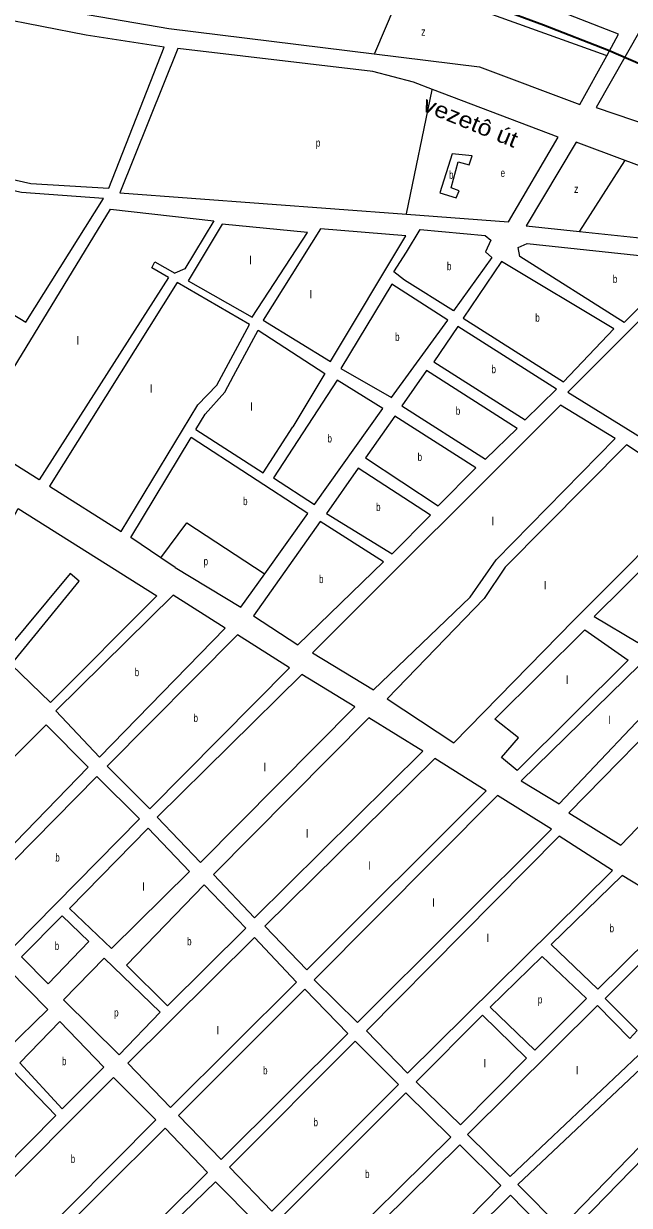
# Model space of a CAD drawing. Extents: x 639657 to 671642, y 222838 to 252123.
# Drawn here: x 657088 to 657845, y 234105 to 235581 of the extents above; entities that cross this region are included whole.
import ezdxf
from ezdxf.enums import TextEntityAlignment as Align

# ---------------------------------------------------------------- set-up
doc = ezdxf.new("R2010")
doc.units = 0
doc.header["$LTSCALE"] = 4
for name, color, linetype, lineweight in [('1', 7, 'Continuous', 13), ('21', 7, 'Continuous', 13), ('57', 7, 'Continuous', 35)]:
    doc.layers.add(name, color=color, linetype=linetype, lineweight=lineweight)
doc.layers.add('22', color=7, linetype='Continuous')
doc.layers.add('7', color=7, linetype='Continuous')

msp = doc.modelspace()

# ---------------------------------------------------------------- linework, layer by layer
at = {"layer": '1'}
for p, q in [((657269.75, 235574.98), (657526.201, 235543.425)), ((657859.39, 235575.31), (657803.218, 235476.576)), ((657944.6, 235370.82), (657839.364, 235410.339)), ((657269.084, 235264.14), (657248.416, 235276.078)), ((657277.55, 234901.85), (657259.832, 234913.783))]:
    msp.add_line(p, q, dxfattribs=at)
for points in [[(656309.705, 235813.299), (656445.06, 235807.97), (657053.16, 235612.8), (657269.75, 235574.98)], [(657194.55, 235375.68), (657263.9, 235551.99), (657166.35, 235566.78), (657055.12, 235588.31), (657016.883, 235600.33), (656903.413, 235635.999)], [(657816.457, 235541.231), (657831.17, 235567.96), (657721.89, 235611.16)], [(657524.2, 235521.65), (657281.04, 235550.05), (657208.54, 235369.83), (657566.169, 235343.122)], [(657526.201, 235543.425), (657657.619, 235527.255), (657782.961, 235480.377), (657816.457, 235541.231)], [(657598.63, 235499.04), (657574.98, 235508.03), (657524.2, 235521.65)], [(656958.68, 235507.97), (656957.78, 235467.15), (656935.92, 235426.78), (657028.98, 235397.06), (657097.28, 235381.75), (657194.55, 235375.68)], [(657566.169, 235343.122), (657693.67, 235333.6), (657755.81, 235439.29), (657598.63, 235499.04)], [(657803.218, 235476.576), (657964.01, 235422.097), (658133.664, 235381.554), (658235.89, 235342.8), (658347.4, 235295.05), (658389.077, 235275.187), (658443.48, 235286.45), (658505.19, 235297.98), (658530.94, 235303.99)], [(657839.364, 235410.339), (657778.3, 235433.27), (657715.84, 235328.67), (657782.481, 235321.648), (658351.682, 235261.67)], [(657022.72, 235064.66), (657196.65, 235349.51), (657325.67, 235334.99), (657289.57, 235275.16), (657277.068, 235269.481)], [(657442.86, 235320.41), (657336.43, 235330.73), (657293.672, 235260.06)], [(657293.672, 235260.06), (657373.772, 235214.612), (657442.86, 235320.41)], [(657248.416, 235276.078), (657252.177, 235283.604), (657277.068, 235269.481)], [(657269.084, 235264.14), (657107.84, 235011.29), (657022.72, 235064.66)], [(657350.435, 235141.234), (657381.293, 235198.304), (657464.57, 235144.32), (657424.56, 235077.55)], [(657303.357, 235074.159), (657314.91, 235093.33), (657339.51, 235121.03), (657350.435, 235141.234)], [(657303.357, 235074.159), (657387.562, 235020.178), (657424.56, 235077.55)], [(657259.832, 234913.783), (657222.05, 234939.23), (657297.38, 235064.24)], [(657389.332, 234893.894), (657443.29, 234969.12), (657297.38, 235064.24)], [(657277.55, 234901.85), (657359.44, 234852.22), (657389.332, 234893.894)]]:
    msp.add_lwpolyline(points, dxfattribs=at)
for points in [[(657085.51, 235370.43), (657026.36, 235383.09), (656962.83, 235286.16), (657091.02, 235208.24), (657188.15, 235362.77)], [(657459.014, 235325), (657387.561, 235210.849), (657471.49, 235159.38), (657565.567, 235316.219)], [(657672.95, 235289.11), (657624.88, 235222.31), (657564.01, 235260.74), (657550.524, 235271.06), (657566.54, 235295.66), (657583.61, 235324.2), (657664.78, 235316.47), (657671.79, 235310.59), (657664.87, 235296.06)], [(657716.94, 235306.47), (657915.83, 235285.24), (657838.25, 235208.12), (657707.87, 235290.32), (657705.68, 235301.59)], [(657762.27, 235133.69), (657825.39, 235200.01), (657684.79, 235284.32), (657637.28, 235213.23)], [(658036.55, 235198.71), (657919.11, 235272.37), (657767.7, 235120.82), (657886.76, 235047.17)], [(657280.11, 235257.773), (657120.77, 235003.28), (657210.2, 234946.7), (657305.7, 235105.01), (657329.49, 235129.74), (657370.458, 235205.589)], [(657617.95, 235211), (657547.91, 235255.84), (657484.42, 235150.3), (657547.44, 235114.03)], [(657753.72, 235124.53), (657630.34, 235202.99), (657600.44, 235158.83), (657714.66, 235086.23)], [(657704.5, 235075.45), (657591.35, 235148.05), (657560.38, 235103.88), (657664.9, 235037.15)], [(657536.75, 235100.56), (657479.65, 235135.78), (657400.11, 235014.07), (657451.3, 234980.43)], [(657827.05, 235063.05), (657758.64, 235104.67), (657449.16, 234795.25), (657525.1, 234749.19), (657646.06, 234865), (657678.33, 234911.51)], [(657606.05, 234978.9), (657653.13, 235026.36), (657551.84, 235090.95), (657514.99, 235038.7)], [(657933.19, 234994.18), (657841.06, 235055.05), (657689.66, 234902.43), (657663.5, 234863.11), (657542.07, 234738.01), (657625.58, 234683.01), (657774.84, 234835.62)], [(657596.43, 234967.05), (657505.91, 235025.77), (657466.39, 234969.21), (657548.28, 234919.05)], [(657800.6, 234840.56), (657855.01, 234808.01), (658004.27, 234957.4), (657950.95, 234989.42)], [(657062.57, 234793.02), (657001.58, 234855.63), (657065.23, 234923.02), (657071.88, 234957.56), (657081.49, 234975.77), (657254.51, 234866.32), (657121.93, 234733.1), (657072.83, 234780.71), (657157.75, 234884.74), (657146.49, 234894.34)], [(657537.58, 234908.8), (657458.38, 234959.51), (657375.31, 234841.53), (657430.56, 234805.24)], [(657128.42, 234722.77), (657182.92, 234664.98), (657340.17, 234826.18), (657275, 234867.27)], [(657676.5, 234712.22), (657788.86, 234823.86), (657843.29, 234785.94), (657704.72, 234648.41), (657684.99, 234664.53), (657706.15, 234689.24)], [(657192.64, 234653.74), (657246.05, 234600.25), (657420.42, 234776.55), (657355.25, 234817.65)], [(657897.15, 234755), (657857.82, 234780.09), (657709.61, 234635.54), (657757.01, 234606.73)], [(657309.18, 234533.37), (657501.74, 234728), (657435.5, 234768.02), (657255.22, 234590.08)], [(657992.5, 234696.3), (657915.99, 234745.41), (657768.88, 234595.49), (657834.07, 234554.93), (657944.79, 234670.32), (657956.66, 234660.17)], [(657169.01, 234652.57), (657116.68, 234705.53), (656957.27, 234545.94), (657012.3, 234491.38)], [(657376.62, 234464.36), (657586.85, 234672.49), (657519.53, 234714.11), (657325.36, 234518.4)], [(657441.9, 234399.1), (657666.03, 234622.86), (657601.93, 234663.42), (657389.56, 234453.67)], [(657233.21, 234587.85), (657179.8, 234640.8), (657022.55, 234481.22), (657075.95, 234428.26)], [(657505.03, 234333.29), (657747.35, 234574.85), (657680.02, 234617.01), (657451.08, 234386.78)], [(657295.26, 234522.04), (657244, 234576.07), (657145.59, 234475.8), (657197.9, 234426.06)], [(657567.61, 234270.17), (657823.42, 234523.55), (657757.05, 234566.29), (657516.35, 234323.14)], [(657872.85, 234494.79), (657835.69, 234517.2), (657746.88, 234430.92), (657805.13, 234375.3), (657900.89, 234469.66)], [(657365.93, 234451.43), (657313.6, 234505.46), (657216.79, 234405.19), (657268.04, 234354.37)], [(657169.93, 234434.54), (657136.49, 234466.63), (657085.68, 234415.41), (657119.13, 234381.71)], [(657814.32, 234363.52), (657917.56, 234466.5), (657993.38, 234422.6), (657695.88, 234141.2), (657642.6, 234193.67), (657804.9, 234354.71), (657845.15, 234313.7), (657854.24, 234323.4)], [(657429.07, 234384.01), (657376.73, 234439.66), (657218.39, 234282.75), (657271.8, 234227.11)], [(657258.94, 234346.28), (657188.82, 234413.67), (657138.01, 234361.91), (657207.6, 234292.91)], [(657791.22, 234363.43), (657735.67, 234415.84), (657670.94, 234352.75), (657726.49, 234298.73)], [(658056.18, 234382.9), (657759.13, 234077.06), (657705.49, 234131.11), (658005.4, 234414.27)], [(657118.517, 234349.857), (657069.09, 234400.31), (657018.28, 234346.94), (657066.659, 234298.897)], [(657493.27, 234319.82), (657439.32, 234374.92), (657281.51, 234217.48), (657334.93, 234162.38)], [(657821.72, 234012.32), (658139.46, 234327.75), (658067.08, 234374.57), (657768.3, 234067.97)], [(657136.44, 234225.5), (657083.55, 234283.29), (657133.56, 234334.87), (657188.33, 234277.8)], [(657633.96, 234205.45), (657716.33, 234289.02), (657661.31, 234342.51), (657578.4, 234259.47)], [(657556.39, 234256.16), (657502.44, 234310.19), (657345.18, 234152.75), (657398.05, 234097.65)], [(657128.42, 234217.41), (657074.46, 234273.59), (656976.05, 234172.23), (657028.93, 234117.13)], [(657253.61, 234212), (657200.74, 234264.96), (657040.26, 234104.29), (657094.21, 234051.33)], [(657565.57, 234245.46), (657621.67, 234190.37), (657462.25, 234032.92), (657408.3, 234088.02)], [(657317.81, 234146.2), (657264.93, 234201.3), (657104.45, 234041.71), (657158.4, 233987.68)], [(657684.24, 234129.93), (657632.99, 234180.74), (657472.51, 234022.22), (657525.92, 233968.19)], [(657379.32, 234082.54), (657328.06, 234134.43), (657166.5, 233978.04), (657220.99, 233921.87)], [(657749.52, 234063.06), (657696.11, 234117.62), (657563.98, 233986.6), (657616.86, 233931.49)]]:
    msp.add_lwpolyline(points, close=True, dxfattribs=at)
at = {"layer": '21'}
for points in [[(657816.457, 235541.231), (657815.538, 235541.564), (657563.928, 235632.415), (657526.413, 235543.925), (657526.201, 235543.425)], [(657566.169, 235343.122), (657566.273, 235343.622), (657598.526, 235498.54), (657598.63, 235499.04)], [(657623.186, 235418.794), (657608.143, 235369.872), (657628.2, 235363.6), (657631.961, 235372.381), (657621.933, 235376.144), (657630.708, 235408.759), (657644.497, 235404.996)], [(657644.497, 235404.996), (657648.257, 235416.285), (657623.186, 235418.794)], [(657782.481, 235321.648), (657782.802, 235322.148), (657839.043, 235409.839), (657839.364, 235410.339)], [(657259.832, 234913.783), (657292.291, 234957.458), (657388.832, 234894.222), (657389.332, 234893.894)]]:
    msp.add_lwpolyline(points, dxfattribs=at)
at = {"layer": '57'}
msp.add_lwpolyline([(657678.934, 235601.436), (657737.328, 235579.845), (657818.572, 235548.093), (657874.427, 235523.962)], dxfattribs=at)

# ---------------------------------------------------------------- texts
at = {"layer": '22', "width": 1.15}
msp.add_text('vezetô út', height=20, rotation=337.88, dxfattribs=at).set_placement((657642.589, 235449.417), align=Align.CENTER)
at = {"layer": '7'}
for s, width, p in [('z', 0.8, (657584.771, 235566.265)), ('p', 0.75, (657453.181, 235427.513)), ('b', 0.75, (657619.425, 235387.434)), ('e', 0.75, (657683.836, 235389.881)), ('z', 0.8, (657775.642, 235369.775)), ('b', 0.75, (657616.865, 235273.255)), ('b', 0.75, (657823.985, 235257.295)), ('b', 0.75, (657727.154, 235209.005)), ('b', 0.75, (657552.126, 235184.935)), ('b', 0.75, (657672.478, 235144.61)), ('b', 0.75, (657627.91, 235092.6)), ('b', 0.75, (657467.719, 235058.105)), ('b', 0.75, (657580.218, 235034.925)), ('b', 0.75, (657362.342, 234979.795)), ('b', 0.75, (657528.397, 234972.41)), ('p', 0.75, (657313.021, 234904.638)), ('b', 0.75, (657457.171, 234882.375)), ('b', 0.75, (657226.993, 234766.125)), ('b', 0.75, (657300.486, 234708.95)), ('b', 0.75, (657127.875, 234534.53)), ('b', 0.75, (657819.896, 234446.25)), ('b', 0.75, (657292.446, 234429.915)), ('b', 0.75, (657127.164, 234424.17)), ('p', 0.75, (657730.333, 234357.285)), ('p', 0.75, (657201.331, 234340.977)), ('b', 0.75, (657136.216, 234280.185)), ('b', 0.75, (657387.304, 234268.65)), ('b', 0.75, (657450.249, 234203.92)), ('b', 0.75, (657147.116, 234158.145)), ('b', 0.75, (657514.632, 234139.19))]:
    msp.add_text(s, height=10, dxfattribs=dict(at, width=width)).set_placement(p)
for p in [(657370.148, 235280.752), (657445.362, 235238.102), (657154.536, 235180.4), (657246.046, 235120.188), (657371.402, 235097.608), (657672.689, 234954.706), (657737.874, 234874.424), (657765.452, 234756.509), (657818.102, 234706.333), (657388.13, 234647.375), (657440.78, 234564.584), (657518.501, 234524.443), (657236.45, 234498.1), (657598.729, 234478.03), (657666.421, 234434.126), (657329.213, 234318.72), (657662.66, 234277.324), (657777.988, 234268.543)]:
    msp.add_text('l', height=10, dxfattribs=at).set_placement(p)

doc.saveas('drawing.dxf')
